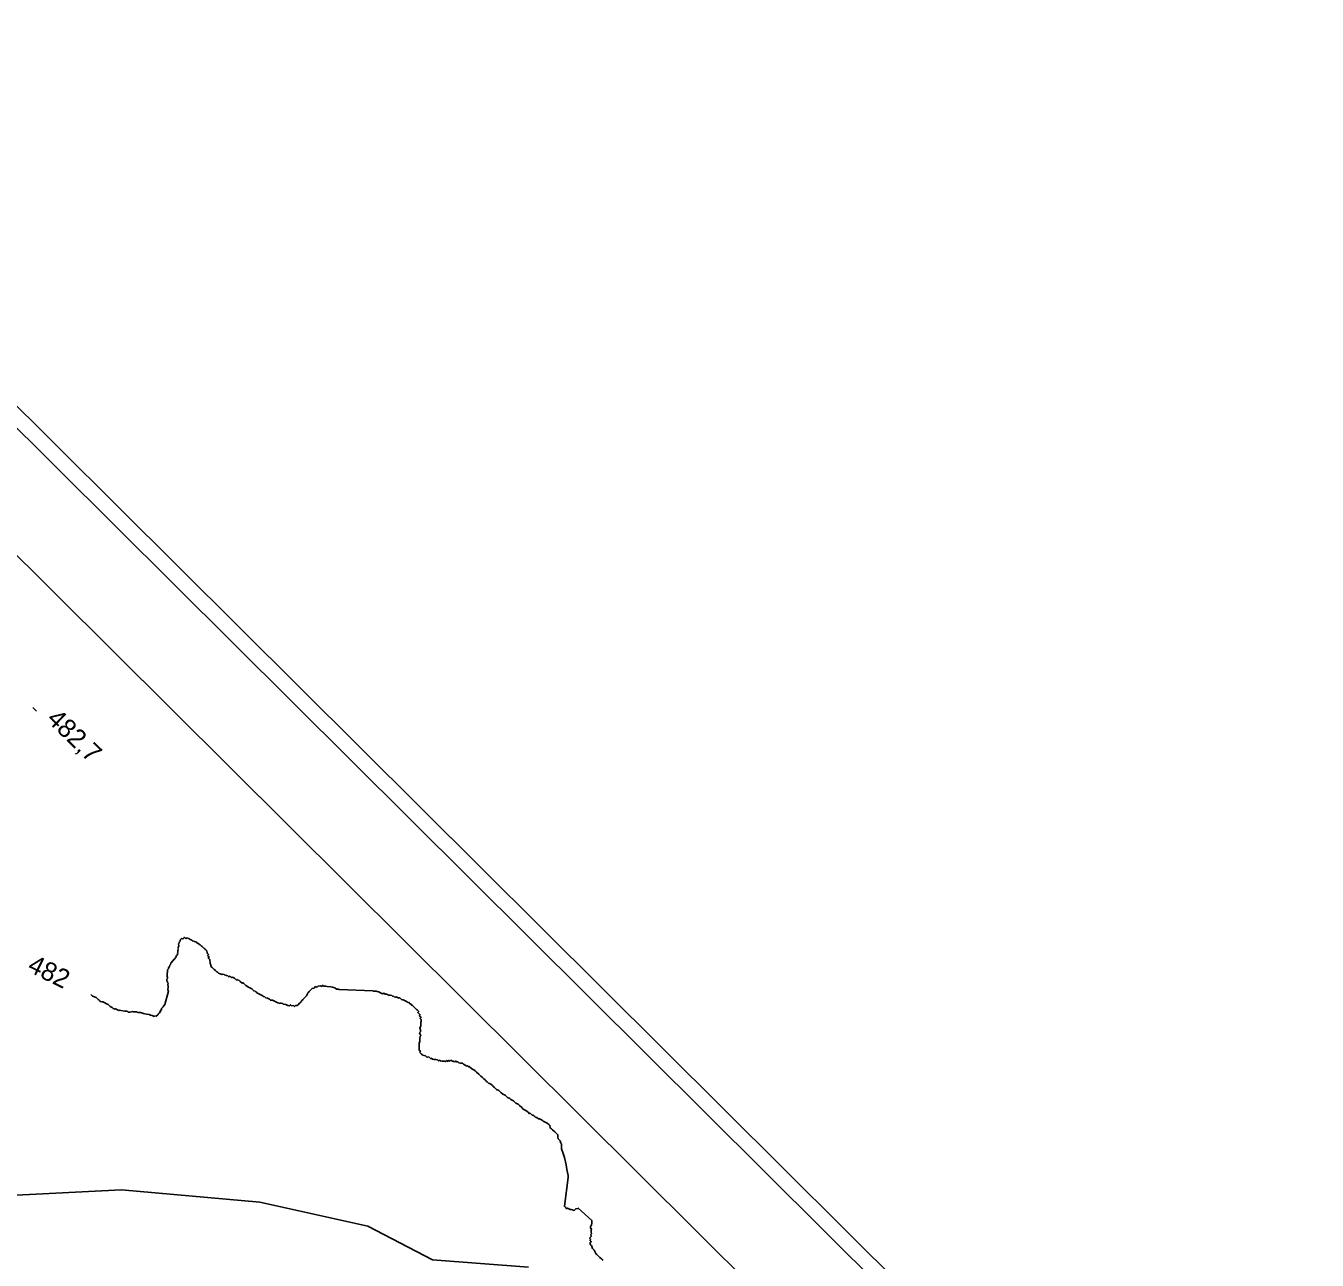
# Model space of a CAD drawing. Extents: x 642515 to 647219, y 6080136 to 6084356.
# Drawn here: x 644267.5 to 644474.6, y 6082865.3 to 6083063.3 of the extents above; entities that cross this region are included whole.
import ezdxf

# ---------------------------------------------------------------- set-up
doc = ezdxf.new("R2010")
doc.units = 0
for name, color, linetype in [('Level 2', 7, 'Continuous'), ('Level 3', 7, 'Continuous'), ('Level 60', 7, 'Continuous'), ('Level 7', 7, 'Continuous')]:
    doc.layers.add(name, color=color, linetype=linetype)

msp = doc.modelspace()

# ---------------------------------------------------------------- linework, layer by layer
at = {"layer": 'Level 2'}
for points in [[(644292.2, 6082916.53), (644292.12, 6082916.44), (644292.05, 6082916.19), (644291.97, 6082916.11), (644291.99, 6082915.78), (644291.91, 6082915.53), (644291.92, 6082915.37), (644291.84, 6082915.28), (644291.93, 6082915.2), (644291.85, 6082915.12), (644291.86, 6082914.95), (644291.86, 6082914.79), (644291.79, 6082914.7), (644291.87, 6082914.63), (644291.79, 6082914.54), (644291.8, 6082914.38), (644291.72, 6082914.29), (644291.64, 6082914.21), (644291.57, 6082914.12), (644291.57, 6082913.96), (644291.49, 6082913.87), (644291.34, 6082913.7), (644291.26, 6082913.61), (644291.03, 6082913.36), (644290.72, 6082913.01), (644290.64, 6082912.76), (644290.57, 6082912.68), (644290.5, 6082912.43), (644290.34, 6082912.26), (644290.35, 6082912.09), (644290.27, 6082912.01), (644290.19, 6082911.92), (644290.2, 6082911.59), (644290.13, 6082911.35), (644290.14, 6082911.18), (644290.15, 6082910.86), (644290.16, 6082910.69), (644290.17, 6082910.53), (644290.09, 6082910.44), (644290.1, 6082910.28), (644290.1, 6082910.12), (644290.19, 6082910.04), (644290.19, 6082909.88), (644290.28, 6082909.8), (644290.21, 6082909.55), (644290.3, 6082909.31), (644290.31, 6082909.14), (644290.24, 6082908.73), (644290.33, 6082908.49), (644289.77, 6082906.33)], [(644298.37, 6082911.36), (644298.2, 6082911.52), (644298.11, 6082911.59), (644298.03, 6082911.67), (644297.86, 6082911.83), (644297.69, 6082911.98), (644297.43, 6082912.21), (644297.35, 6082912.29), (644297.26, 6082912.37), (644297.18, 6082912.45), (644297.08, 6082912.85), (644297, 6082912.93), (644296.97, 6082913.58), (644296.8, 6082913.74), (644296.71, 6082913.81), (644296.87, 6082913.98), (644296.7, 6082914.14), (644296.62, 6082914.22), (644296.77, 6082914.39), (644296.6, 6082914.54), (644296.52, 6082914.62), (644296.5, 6082914.95), (644296.33, 6082915.1), (644296.25, 6082915.18), (644296.17, 6082915.26), (644296, 6082915.41), (644295.83, 6082915.57), (644295.74, 6082915.64), (644295.66, 6082915.72), (644295.49, 6082915.88), (644295.4, 6082915.95), (644294.99, 6082916.18), (644294.9, 6082916.26), (644294.82, 6082916.33), (644294.73, 6082916.41), (644294.48, 6082916.48), (644294.4, 6082916.56), (644294.32, 6082916.47), (644294.07, 6082916.7), (644293.73, 6082916.85), (644293.65, 6082916.93), (644293.4, 6082917), (644293.32, 6082917.07), (644293.24, 6082916.99), (644293.16, 6082916.9), (644292.91, 6082917.14), (644292.83, 6082917.05), (644292.75, 6082916.96), (644292.67, 6082916.88), (644292.43, 6082916.95), (644292.27, 6082916.78), (644292.2, 6082916.53)], [(644307.93, 6082906.7), (644307.86, 6082906.61), (644307.36, 6082906.91), (644307.02, 6082907.06), (644306.7, 6082907.04), (644306.53, 6082907.2), (644306.2, 6082907.35), (644305.95, 6082907.42), (644305.78, 6082907.57), (644305.53, 6082907.64), (644305.45, 6082907.72), (644305.36, 6082907.79), (644305.03, 6082907.94), (644304.95, 6082908.02), (644304.53, 6082908.24), (644304.44, 6082908.32), (644304.36, 6082908.4), (644304.27, 6082908.47), (644304.03, 6082908.54), (644303.86, 6082908.7), (644303.69, 6082908.85), (644303.27, 6082909.08), (644303.19, 6082909.15), (644302.77, 6082909.38), (644302.51, 6082909.61), (644302.35, 6082909.77), (644302.26, 6082909.84), (644302.18, 6082909.76), (644301.84, 6082910.07), (644301.67, 6082910.22), (644301.59, 6082910.3), (644301.51, 6082910.21), (644301.34, 6082910.37), (644301.26, 6082910.28), (644301.01, 6082910.52), (644300.93, 6082910.59), (644300.59, 6082910.74), (644300.52, 6082910.65), (644300.35, 6082910.81), (644300.1, 6082910.88), (644300.02, 6082910.79), (644299.85, 6082910.95), (644299.6, 6082911.02), (644299.52, 6082911.09), (644299.44, 6082911.01), (644299.27, 6082911.16), (644299.02, 6082911.23), (644298.95, 6082911.15), (644298.61, 6082911.29), (644298.37, 6082911.36)], [(644289.77, 6082906.33), (644289.54, 6082906.08), (644289.46, 6082905.99), (644289.23, 6082905.73), (644289.23, 6082905.57), (644289, 6082905.31), (644289.08, 6082905.24), (644288.85, 6082904.98), (644288.69, 6082904.81), (644288.62, 6082904.72), (644288.38, 6082904.46), (644288.13, 6082904.53), (644288.06, 6082904.45), (644287.72, 6082904.59), (644287.48, 6082904.66), (644287.23, 6082904.73), (644286.82, 6082904.79), (644286.57, 6082904.86), (644286.32, 6082904.93), (644285.83, 6082905.07), (644285.5, 6082905.05), (644285.17, 6082905.2), (644284.68, 6082905.17), (644284.6, 6082905.25), (644284.2, 6082905.15), (644283.87, 6082905.13), (644283.7, 6082905.29), (644283.38, 6082905.27), (644282.72, 6082905.4), (644282.47, 6082905.47), (644282.39, 6082905.38), (644282.06, 6082905.53), (644281.89, 6082905.68), (644281.81, 6082905.6), (644281.48, 6082905.74), (644281.31, 6082905.9), (644280.98, 6082906.04), (644280.81, 6082906.2), (644280.72, 6082906.28), (644280.64, 6082906.35), (644280.31, 6082906.5), (644280.22, 6082906.58), (644279.81, 6082906.8), (644279.64, 6082906.79), (644279.4, 6082906.86), (644279.31, 6082906.94), (644279.14, 6082907.1), (644279.06, 6082907.17), (644278.8, 6082907.41), (644278.72, 6082907.48), (644278.14, 6082907.7), (644277.86, 6082907.95)], [(644317.05, 6082909.05), (644316.64, 6082909.11), (644316.39, 6082909.18), (644315.82, 6082909.23), (644315.57, 6082909.3), (644315.25, 6082909.29), (644315.08, 6082909.44), (644314.92, 6082909.27), (644314.67, 6082909.34), (644314.35, 6082909.32), (644314.19, 6082909.15), (644313.94, 6082909.22), (644313.71, 6082908.96), (644313.38, 6082908.94), (644313.07, 6082908.6), (644312.99, 6082908.52), (644312.92, 6082908.43), (644312.84, 6082908.34), (644312.76, 6082908.26), (644312.68, 6082908.17), (644312.53, 6082907.84), (644312.46, 6082907.75), (644312.38, 6082907.66), (644312.3, 6082907.58), (644312.14, 6082907.41), (644312.07, 6082907.32), (644311.91, 6082907.15), (644311.83, 6082907.06), (644311.75, 6082906.98), (644311.68, 6082906.89), (644311.6, 6082906.81), (644311.52, 6082906.72), (644311.44, 6082906.63), (644311.36, 6082906.55), (644311.13, 6082906.29), (644311.05, 6082906.21), (644310.73, 6082906.19), (644310.57, 6082906.02), (644310.4, 6082906.17), (644310.08, 6082906.16), (644309.91, 6082906.31), (644309.83, 6082906.22), (644309.75, 6082906.14), (644309.5, 6082906.21), (644309.26, 6082906.28), (644309.17, 6082906.35), (644308.76, 6082906.41), (644308.68, 6082906.49), (644308.43, 6082906.56), (644308.27, 6082906.55), (644308.1, 6082906.54), (644307.93, 6082906.7)], [(644330.87, 6082903.96), (644330.7, 6082904.11), (644330.86, 6082904.28), (644330.6, 6082904.51), (644330.67, 6082904.76), (644330.5, 6082904.92), (644330.34, 6082905.07), (644330.49, 6082905.25), (644330.24, 6082905.48), (644330.15, 6082905.55), (644330.07, 6082905.63), (644329.98, 6082905.71), (644329.9, 6082905.79), (644329.81, 6082905.86), (644329.64, 6082906.02), (644329.48, 6082906.17), (644329.39, 6082906.25), (644328.97, 6082906.64), (644328.88, 6082906.72), (644328.8, 6082906.63), (644328.63, 6082906.79), (644328.55, 6082906.86), (644328.3, 6082906.93), (644327.97, 6082907.08), (644327.72, 6082907.15), (644327.55, 6082907.3), (644327.38, 6082907.46), (644327.31, 6082907.37), (644326.97, 6082907.52), (644326.89, 6082907.6), (644326.81, 6082907.51), (644326.56, 6082907.58), (644326.4, 6082907.73), (644326.32, 6082907.65), (644326.15, 6082907.8), (644325.9, 6082907.87), (644325.57, 6082907.85), (644325.41, 6082908.01), (644325.08, 6082907.99), (644324.91, 6082908.15), (644324.67, 6082908.05), (644324.25, 6082908.28), (644324.17, 6082908.36), (644323.67, 6082908.49), (644323.19, 6082908.47), (644323.1, 6082908.55), (644317.71, 6082908.76), (644317.63, 6082908.84), (644317.3, 6082908.82), (644317.05, 6082909.05)], [(644336.29, 6082897.12), (644336.12, 6082897.27), (644336.04, 6082897.19), (644335.62, 6082897.41), (644335.47, 6082897.24), (644335.3, 6082897.39), (644335.22, 6082897.31), (644335.14, 6082897.22), (644334.97, 6082897.38), (644334.89, 6082897.29), (644334.82, 6082897.21), (644334.57, 6082897.28), (644334.24, 6082897.26), (644334, 6082897.33), (644333.75, 6082897.4), (644333.67, 6082897.31), (644333.5, 6082897.47), (644333.25, 6082897.53), (644333.09, 6082897.53), (644332.93, 6082897.52), (644332.68, 6082897.59), (644332.51, 6082897.74), (644332.43, 6082897.66), (644332.18, 6082897.89), (644331.93, 6082897.96), (644331.85, 6082897.87), (644331.6, 6082898.1), (644331.35, 6082898.17), (644331.11, 6082898.24), (644331.02, 6082898.32), (644330.94, 6082898.4), (644330.85, 6082898.47), (644330.77, 6082898.55), (644330.68, 6082898.63), (644330.75, 6082898.88), (644330.58, 6082899.03), (644330.56, 6082899.69), (644330.54, 6082900.18), (644330.69, 6082900.35), (644330.67, 6082900.84), (644330.74, 6082901.25), (644330.82, 6082901.34), (644330.63, 6082901.82), (644330.79, 6082901.99), (644330.78, 6082902.31), (644330.68, 6082902.56), (644330.76, 6082902.8), (644330.83, 6082902.89), (644330.82, 6082903.22), (644330.81, 6082903.54), (644330.88, 6082903.63), (644330.87, 6082903.96)], [(644344.5, 6082891.65), (644344.33, 6082891.81), (644344, 6082891.95), (644343.91, 6082892.03), (644343.74, 6082892.19), (644343.66, 6082892.26), (644343.32, 6082892.57), (644342.99, 6082892.72), (644342.9, 6082892.8), (644342.73, 6082892.95), (644342.65, 6082893.03), (644342.56, 6082893.11), (644342.48, 6082893.19), (644342.39, 6082893.26), (644342.31, 6082893.34), (644342.06, 6082893.57), (644341.97, 6082893.65), (644341.89, 6082893.73), (644341.81, 6082893.64), (644341.55, 6082893.87), (644341.47, 6082893.95), (644341.38, 6082894.03), (644341.3, 6082894.11), (644341.22, 6082894.18), (644341.13, 6082894.26), (644340.96, 6082894.42), (644340.79, 6082894.57), (644340.71, 6082894.65), (644340.45, 6082894.88), (644340.2, 6082895.11), (644340.11, 6082895.19), (644339.78, 6082895.5), (644339.52, 6082895.73), (644339.35, 6082895.89), (644339.02, 6082896.03), (644338.6, 6082896.42), (644338.52, 6082896.33), (644338.35, 6082896.49), (644338.27, 6082896.57), (644338.19, 6082896.48), (644337.69, 6082896.78), (644337.6, 6082896.86), (644337.52, 6082896.94), (644337.19, 6082896.92), (644336.94, 6082896.99), (644336.77, 6082897.14), (644336.61, 6082897.14), (644336.44, 6082897.29), (644336.36, 6082897.2), (644336.29, 6082897.12)], [(644353.39, 6082883.53), (644353.37, 6082884.02), (644353.28, 6082884.09), (644353.18, 6082884.5), (644352.84, 6082884.81), (644352.83, 6082885.13), (644352.82, 6082885.46), (644352.65, 6082885.61), (644352.56, 6082885.69), (644352.48, 6082885.77), (644352.39, 6082885.85), (644352.31, 6082885.92), (644351.97, 6082886.23), (644351.8, 6082886.39), (644351.63, 6082886.54), (644351.55, 6082886.62), (644351.53, 6082886.95), (644351.45, 6082887.02), (644351.37, 6082887.1), (644351.11, 6082887.33), (644350.86, 6082887.4), (644350.69, 6082887.56), (644350.45, 6082887.63), (644350.28, 6082887.78), (644349.86, 6082888.01), (644349.7, 6082888), (644349.44, 6082888.23), (644349.28, 6082888.22), (644349.11, 6082888.38), (644349.03, 6082888.45), (644348.86, 6082888.61), (644348.7, 6082888.6), (644348.36, 6082888.91), (644348.28, 6082888.82), (644348.03, 6082889.06), (644347.86, 6082889.21), (644347.69, 6082889.37), (644347.27, 6082889.59), (644347.02, 6082889.82), (644346.68, 6082890.13), (644346.59, 6082890.21), (644346.51, 6082890.29), (644346.42, 6082890.36), (644346.09, 6082890.51), (644346.01, 6082890.59), (644345.67, 6082890.9), (644345.25, 6082891.12), (644345.17, 6082891.2), (644345.08, 6082891.28), (644345, 6082891.35), (644344.75, 6082891.42), (644344.5, 6082891.65)], [(644359.15, 6082866.17), (644359.06, 6082866.25), (644358.98, 6082866.32), (644358.62, 6082866.96), (644358.54, 6082867.04), (644358.45, 6082867.11), (644358.37, 6082867.19), (644358.19, 6082867.67), (644358.1, 6082867.75), (644358.02, 6082867.83), (644358.01, 6082868.15), (644358.16, 6082868.32), (644357.99, 6082868.48), (644358.06, 6082868.73), (644357.89, 6082868.88), (644358.05, 6082869.05), (644358.13, 6082869.14), (644358.11, 6082869.47), (644358.19, 6082869.55), (644358.18, 6082869.88), (644358.17, 6082870.2), (644358.24, 6082870.29), (644358.07, 6082870.45), (644358.06, 6082870.77), (644358.22, 6082870.94), (644358.28, 6082871.35), (644358.27, 6082871.68), (644356.07, 6082873.69), (644355.99, 6082873.61), (644355.67, 6082873.59), (644355.51, 6082873.42), (644355.43, 6082873.33), (644355.18, 6082873.4), (644354.94, 6082873.47), (644354.77, 6082873.46), (644354.69, 6082873.54), (644354.44, 6082873.61), (644354.36, 6082873.69), (644354.28, 6082873.6), (644354.11, 6082873.75), (644354.03, 6082873.83), (644353.86, 6082873.99), (644354.48, 6082878.6), (644354.47, 6082878.92), (644354.27, 6082879.89), (644354.16, 6082880.62), (644353.86, 6082881.83), (644353.67, 6082882.48), (644353.4, 6082883.2), (644353.39, 6082883.53)], [(644360.08, 6082865.32), (644359.99, 6082865.4), (644359.82, 6082865.55), (644359.57, 6082865.78), (644359.31, 6082866.01), (644359.23, 6082866.09), (644359.15, 6082866.17)]]:
    msp.add_lwpolyline(points, dxfattribs=at)
at = {"layer": 'Level 3'}
msp.add_line((644268.6, 6082953.99), (644269.18, 6082953.43), dxfattribs=at)
at = {"layer": 'Level 60'}
for points in [[(643756.15, 6083509.1), (645893.11, 6081385.05), (644652.25, 6080135.58), (642514.75, 6082260.08)], [(642518.29, 6082260.09), (643756.16, 6083505.56), (645889.57, 6081385.04), (644651.74, 6080139.63)], [(643756.23, 6083485.06), (645517.55, 6081734.46), (644300.6, 6080509.08), (642538.79, 6082260.16)]]:
    msp.add_lwpolyline(points, close=True, dxfattribs=at)
at = {"layer": 'Level 7'}
msp.add_lwpolyline([(644087.06, 6082933.6), (644097.23, 6082942.52), (644106.28, 6082954.02), (644123.78, 6082966.61), (644139.85, 6082965.79), (644152.98, 6082961.7), (644166.11, 6082954.47), (644179.29, 6082949.39), (644194.42, 6082947.54), (644207.9, 6082942.81), (644215.36, 6082934.47), (644218.5, 6082924.11), (644219.93, 6082915.3), (644227.16, 6082908.11), (644234.95, 6082902.6), (644235.67, 6082898.2), (644243.13, 6082889.54), (644254.78, 6082878.97), (644264.9, 6082875.72), (644282.82, 6082876.64), (644304.97, 6082874.66), (644322.31, 6082870.79), (644332.71, 6082865.42), (644348.11, 6082864.24)], dxfattribs=at)

# ---------------------------------------------------------------- texts
at = {"layer": 'Level 2'}
msp.add_text('482', height=3, rotation=333.754, dxfattribs=at).set_placement((644267.54, 6082911.78))
at = {"layer": 'Level 3'}
msp.add_text('482,7', height=3, rotation=315.59, dxfattribs=at).set_placement((644270.63, 6082951.95))

doc.saveas('drawing.dxf')
